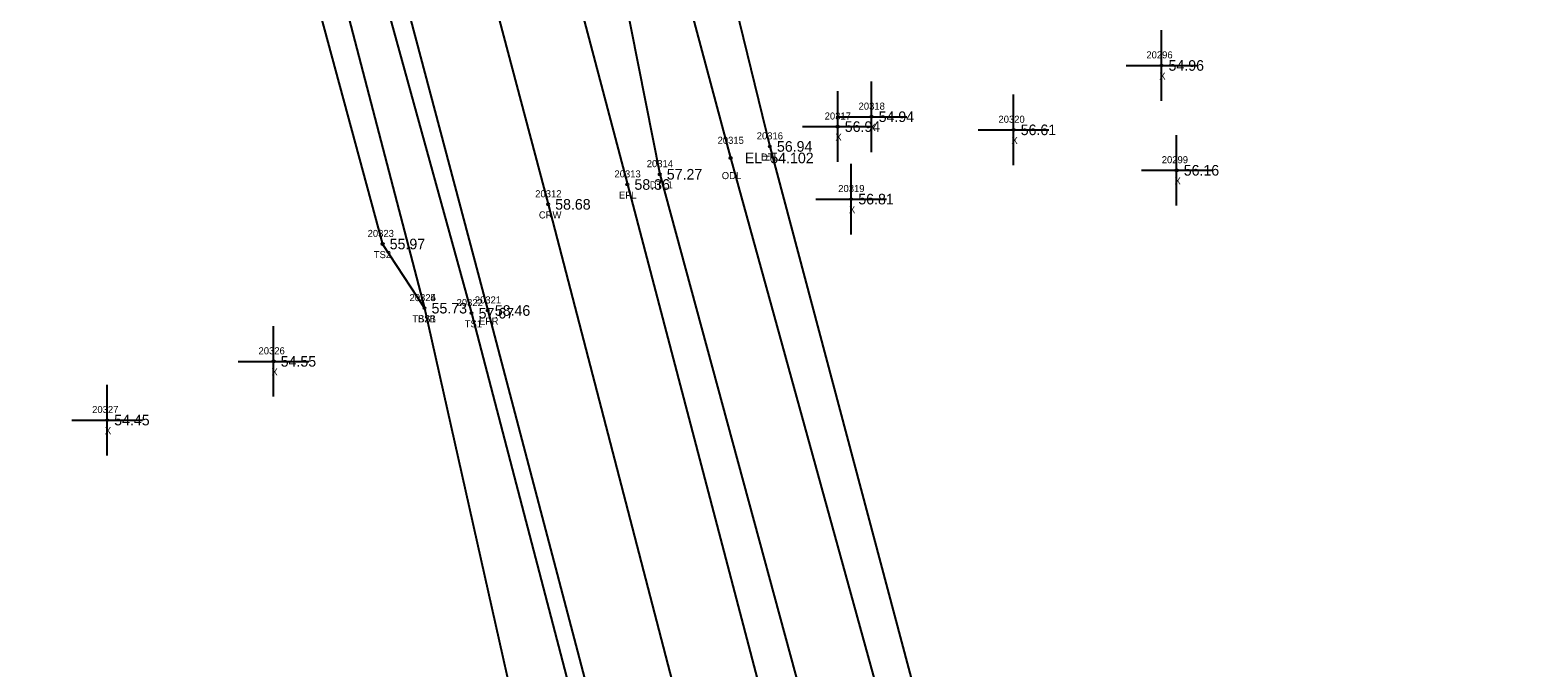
# Model space of a CAD drawing. Extents: x 2396547 to 2397655, y 770185 to 772649.
# Drawn here: x 2396920.4 to 2397133.8, y 771552 to 771642.4 of the extents above; entities that cross this region are included whole.
import ezdxf

# ---------------------------------------------------------------- set-up
doc = ezdxf.new("R2010")
doc.units = 0
for name, color, linetype in [('RD_DTM_BkLn1', 7, 'Continuous'), ('RD_DTM_BkLn2', 7, 'Continuous'), ('RD_DTM_BkLn_txCode', 7, 'Continuous'), ('RD_EX_H2O', 7, 'Continuous'), ('RD_EX_H2O_txCode', 7, 'Continuous'), ('RD_EX_Misc', 7, 'Continuous'), ('RD_EX_Misc_txCode', 7, 'Continuous'), ('RD_EX_Road', 7, 'Continuous'), ('RD_EX_Road_txCode', 7, 'Continuous'), ('RD_EX_TX_H2O_ELEV', 7, 'Continuous'), ('RD_EX_TX_Misc_ELEV', 7, 'Continuous'), ('RD_EX_TX_Road_ELEV', 7, 'Continuous'), ('RD_HC_Survey_ELEV', 7, 'Continuous'), ('RD_HC_Survey_txCode', 7, 'Continuous'), ('RD_SMD_Locator', 7, 'Continuous')]:
    doc.layers.add(name, color=color, linetype=linetype)

msp = doc.modelspace()

# ---------------------------------------------------------------- linework, layer by layer
at = {"layer": 'RD_DTM_BkLn1'}
msp.add_lwpolyline([(2396669.86, 772614.94), (2396704.28, 772521.49), (2396739.29, 772426.89), (2396775.36, 772328.69), (2396800.21, 772259.35), (2396825.58, 772185.8), (2396852.46, 772104.52), (2396872.48, 772041.55), (2396897.57, 771959.72), (2396918.76, 771888.68), (2396939.09, 771818.34), (2396959.29, 771747.62), (2396993.72, 771617.68), (2397022.56, 771506.67), (2397049.1, 771404.69)], dxfattribs=at)
at = {"layer": 'RD_DTM_BkLn2'}
for points in [[(2396921.95, 771810.18), (2396943.94, 771743.58), (2396982.88, 771602.26), (2397008.66, 771503.58), (2397035.9, 771402.4)], [(2396921.95, 771810.18), (2396927.42, 771791.88), (2396939.93, 771742.16), (2396976.22, 771602.97), (2396999, 771501.35), (2397026.41, 771393.39)], [(2396927.42, 771791.88), (2396925.8, 771777.21), (2396935.43, 771740.83), (2396970.29, 771612.06), (2396976.22, 771602.97)]]:
    msp.add_lwpolyline(points, dxfattribs=at)
at = {"layer": 'RD_EX_H2O'}
for points in [[(2397132.06, 771727.73), (2397069.65, 771707.99), (2397027.41, 771693.94), (2396997.29, 771683.71), (2397009.52, 771621.94), (2397039.8, 771510.33), (2397059.22, 771428.3), (2397068.26, 771415.82), (2397065.8, 771409.74)], [(2397133.23, 771725), (2397070.25, 771705.35), (2397027.65, 771692.13), (2397008.03, 771684.24), (2397003.46, 771682.97), (2397004.86, 771679.14), (2397019.55, 771624.25), (2397050.23, 771512.98), (2397072.95, 771431.23), (2397072.81, 771420.44), (2397072.44, 771413.81)], [(2397133.83, 771721.66), (2397071.25, 771701.52), (2397031.62, 771688.97), (2397008.91, 771681.79), (2397013.82, 771672.05), (2397025.11, 771625.88), (2397054.64, 771514.68), (2397075.97, 771429.94), (2397072.44, 771413.81)]]:
    msp.add_lwpolyline(points, dxfattribs=at)
at = {"layer": 'RD_EX_Misc'}
for p, q in [((2397080.55, 771632.35), (2397080.55, 771642.35)), ((2397075.55, 771637.35), (2397085.55, 771637.35)), ((2397034.71, 771623.69), (2397034.71, 771633.69)), ((2397039.51, 771625.09), (2397039.51, 771635.09)), ((2397059.62, 771623.23), (2397059.62, 771633.23)), ((2397034.51, 771630.09), (2397044.51, 771630.09)), ((2397029.71, 771628.69), (2397039.71, 771628.69)), ((2397054.62, 771628.23), (2397064.62, 771628.23)), ((2397082.7, 771617.5), (2397082.7, 771627.5)), ((2397036.63, 771613.42), (2397036.63, 771623.42)), ((2397077.7, 771622.5), (2397087.7, 771622.5)), ((2397031.63, 771618.42), (2397041.63, 771618.42)), ((2396954.86, 771590.44), (2396954.86, 771600.44)), ((2396949.86, 771595.44), (2396959.86, 771595.44)), ((2396931.29, 771582.12), (2396931.29, 771592.12)), ((2396926.29, 771587.12), (2396936.29, 771587.12))]:
    msp.add_line(p, q, dxfattribs=at)
at = {"layer": 'RD_EX_Road'}
for points in [[(2396680.92, 772617.84), (2396715.6, 772525.73), (2396750.68, 772430.62), (2396786.3, 772332.21), (2396811.38, 772263.31), (2396839.69, 772181.74), (2396863.75, 772109.83), (2396883.63, 772046.56), (2396889.54, 772027.11), (2396896.25, 772004.37), (2396904.34, 771978.33), (2396908.24, 771964.89), (2396921.74, 771919.68), (2396927.03, 771902.11), (2396950.2, 771821.74), (2396970.47, 771750.68), (2396978.33, 771721.29), (2396990.58, 771675.04), (2397004.94, 771620.49), (2397034.26, 771508.8), (2397061.11, 771410.49), (2397060.64, 771407.04), (2397062.07, 771407.67)], [(2396658.78, 772611.07), (2396693.37, 772516.9), (2396729.65, 772418.78), (2396760.7, 772333.11), (2396788.58, 772254.87), (2396814.65, 772181.57), (2396841.1, 772100.86), (2396861.19, 772037.76), (2396886.09, 771955.71), (2396907.15, 771884.49), (2396928.56, 771811.72), (2396947.65, 771744.09), (2396985.17, 771602.64), (2397011.11, 771504.04), (2397037.95, 771404.25), (2397039, 771401.22)]]:
    msp.add_lwpolyline(points, dxfattribs=at)
at = {"layer": 'RD_SMD_Locator'}
for centre in [(2397080.55, 771637.35), (2397034.71, 771628.69), (2397039.51, 771630.09), (2397059.62, 771628.23), (2397025.11, 771625.88), (2397019.55, 771624.25), (2397082.7, 771622.5), (2397004.94, 771620.49), (2397009.52, 771621.94), (2397036.63, 771618.42), (2396993.72, 771617.68), (2396970.29, 771612.06), (2396976.22, 771602.97), (2396976.22, 771602.97), (2396982.88, 771602.26), (2396985.17, 771602.64), (2396954.86, 771595.44), (2396931.29, 771587.12)]:
    msp.add_circle(centre, 0.15, dxfattribs=at)

# ---------------------------------------------------------------- texts
at = {"layer": 'RD_DTM_BkLn_txCode'}
for s, p in [('20323', (2396968.17, 771613.06)), ('TS2', (2396969.04, 771610.06)), ('20324', (2396974.1, 771603.97)), ('20325', (2396974.1, 771603.97)), ('20322', (2396980.76, 771603.26)), ('TS2B', (2396974.5, 771600.97)), ('BS1', (2396975.28, 771600.97)), ('TS1', (2396981.91, 771600.26))]:
    msp.add_text(s, height=1, dxfattribs=at).set_placement(p)
at = {"layer": 'RD_EX_H2O_txCode'}
for s, p in [('20315', (2397017.71, 771626.25)), ('20316', (2397023.25, 771626.88)), ('DTL', (2397023.86, 771623.88)), ('20314', (2397007.68, 771622.94)), ('DTL1', (2397008.11, 771619.94)), ('ODL', (2397018.3, 771621.25))]:
    msp.add_text(s, height=1, dxfattribs=at).set_placement(p)
at = {"layer": 'RD_EX_Misc_txCode'}
for s, p in [('20296', (2397078.41, 771638.35)), ('X', (2397080.24, 771635.35)), ('20318', (2397037.67, 771631.09)), ('20317', (2397032.87, 771629.69)), ('X', (2397039.19, 771628.09)), ('20320', (2397057.47, 771629.23)), ('X', (2397034.39, 771626.69)), ('X', (2397059.31, 771626.23)), ('20299', (2397080.59, 771623.5)), ('20319', (2397034.79, 771619.42)), ('X', (2397082.39, 771620.5)), ('X', (2397036.31, 771616.42)), ('20326', (2396952.72, 771596.44)), ('X', (2396954.55, 771593.44)), ('20327', (2396929.17, 771588.12)), ('X', (2396930.97, 771585.12))]:
    msp.add_text(s, height=1, dxfattribs=at).set_placement(p)
at = {"layer": 'RD_EX_Road_txCode'}
for s, p in [('20313', (2397003.11, 771621.49)), ('EPL', (2397003.74, 771618.49)), ('20321', (2396983.34, 771603.64)), ('EPR', (2396983.94, 771600.64))]:
    msp.add_text(s, height=1, dxfattribs=at).set_placement(p)
at = {"layer": 'RD_EX_TX_H2O_ELEV'}
for s, p in [('56.94', (2397026.11, 771625.13)), ('EL=54.102', (2397021.55, 771623.5)), ('57.27', (2397010.52, 771621.19))]:
    msp.add_text(s, height=1.5, dxfattribs=at).set_placement(p)
at = {"layer": 'RD_EX_TX_Misc_ELEV'}
for s, p in [('54.96', (2397081.55, 771636.6)), ('54.94', (2397040.51, 771629.34)), ('56.94', (2397035.71, 771627.94)), ('56.61', (2397060.62, 771627.48)), ('56.16', (2397083.7, 771621.75)), ('56.81', (2397037.63, 771617.67)), ('55.97', (2396971.29, 771611.31)), ('55.73', (2396977.22, 771602.22)), ('55.73', (2396977.22, 771602.22)), ('57.67', (2396983.88, 771601.51)), ('54.55', (2396955.86, 771594.69)), ('54.45', (2396932.29, 771586.37))]:
    msp.add_text(s, height=1.5, dxfattribs=at).set_placement(p)
at = {"layer": 'RD_EX_TX_Road_ELEV'}
for s, p in [('58.36', (2397005.94, 771619.74)), ('58.46', (2396986.17, 771601.89))]:
    msp.add_text(s, height=1.5, dxfattribs=at).set_placement(p)
at = {"layer": 'RD_HC_Survey_ELEV'}
msp.add_text('58.68', height=1.5, dxfattribs=at).set_placement((2396994.72, 771616.93))
at = {"layer": 'RD_HC_Survey_txCode'}
for s, p in [('20312', (2396991.89, 771618.68)), ('CRW', (2396992.41, 771615.68))]:
    msp.add_text(s, height=1, dxfattribs=at).set_placement(p)

doc.saveas('drawing.dxf')
